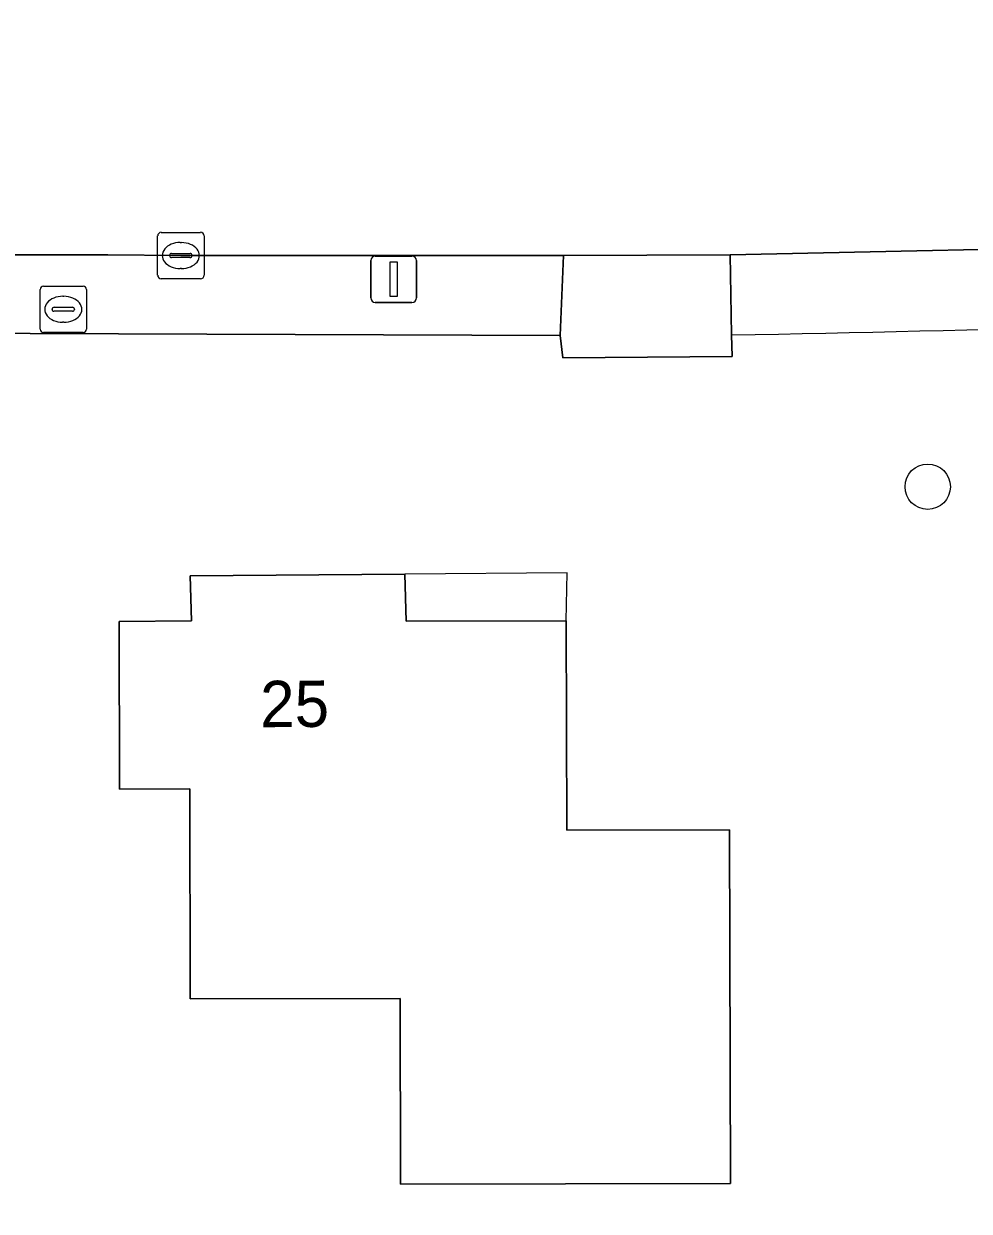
# Model space of a CAD drawing. Extents: x 162661 to 163484, y 380247 to 381230.
# Drawn here: x 163108.1 to 163128.5, y 380811.86 to 380837.48 of the extents above; entities that cross this region are included whole.
import ezdxf

# ---------------------------------------------------------------- set-up
doc = ezdxf.new("R2010")
doc.units = 0
for name, color, linetype in [('IMGEO_Boom', 7, 'Continuous'), ('IMGEO_Brandkraan', 7, 'Continuous'), ('IMGEO_Erf', 7, 'Continuous'), ('IMGEO_Kolk', 7, 'Continuous'), ('IMGEO_Lichtmast', 7, 'Continuous'), ('IMGEO_Pand', 7, 'Continuous'), ('IMGEO_Pand_nummerreeks', 7, 'Continuous'), ('IMGEO_Pand_overbouw', 7, 'Continuous'), ('IMGEO_Parkeervlak_halfverhard', 7, 'Continuous'), ('IMGEO_Rijbaan_lokaal_gesloten', 7, 'Continuous'), ('IMGEO_Voetpad_open', 7, 'Continuous')]:
    doc.layers.add(name, color=color, linetype=linetype)

msp = doc.modelspace()

# ---------------------------------------------------------------- linework, layer by layer
at = {"layer": 'IMGEO_Boom'}
msp.add_circle((163127.605, 380827.492), 0.489, dxfattribs=at)
at = {"layer": 'IMGEO_Brandkraan'}
for p, q in [((163108.452, 380830.893), (163108.452, 380831.745)), ((163108.527, 380831.819), (163109.379, 380831.819)), ((163109.453, 380831.745), (163109.453, 380830.893)), ((163108.94, 380831.599), (163108.965, 380831.599)), ((163108.711, 380831.313), (163108.711, 380831.325)), ((163109.149, 380831.276), (163108.751, 380831.276)), ((163108.754, 380831.362), (163109.152, 380831.362)), ((163109.195, 380831.325), (163109.195, 380831.313)), ((163108.963, 380831.039), (163108.938, 380831.039)), ((163109.379, 380830.819), (163108.527, 380830.819))]:
    msp.add_line(p, q, dxfattribs=at)
for points in [[(163108.452, 380830.893), (163108.452, 380831.745)], [(163108.527, 380831.819), (163109.379, 380831.819)], [(163109.453, 380831.745), (163109.453, 380830.893)], [(163109.379, 380830.819), (163108.527, 380830.819)]]:
    msp.add_lwpolyline(points, dxfattribs=at)
for centre, radius, start, end in [((163108.529, 380831.743), 0.0765, 91.552, 178.448), ((163108.529, 380831.743), 0.0765, 91.552, 178.448), ((163109.377, 380831.743), 0.0765, 1.552, 88.448), ((163109.377, 380831.743), 0.0765, 1.552, 88.448), ((163108.751, 380831.322), 0.0403, 85.8775, 175.7526), ((163108.748, 380831.312), 0.0366, 178.938, 274.7102), ((163109.152, 380831.319), 0.043, 264.8664, 352.4533), ((163109.156, 380831.324), 0.0386, 1.7309, 96.639), ((163108.529, 380830.895), 0.0765, 181.552, 268.448), ((163108.529, 380830.895), 0.0765, 181.552, 268.448), ((163109.377, 380830.895), 0.0765, 271.552, 358.448), ((163109.377, 380830.895), 0.0765, 271.552, 358.448)]:
    msp.add_arc(centre, radius, start, end, dxfattribs=at)
for centre, major_axis, ratio, start_param, end_param in [((163108.939, 380831.319), (-0.387, 0.002), 0.722429, 4.712389, 7.853982), ((163108.964, 380831.319), (-0.39, 0.002), 0.717154, 1.570796, 4.712389)]:
    msp.add_ellipse(centre, major_axis=major_axis, ratio=ratio, start_param=start_param, end_param=end_param, dxfattribs=at)
at = {"layer": 'IMGEO_Erf'}
msp.add_lwpolyline([(163123.374, 380830.767), (163123.388, 380830.302), (163119.732, 380830.269), (163119.673, 380830.754), (163106.322, 380830.801), (163103.397, 380830.811), (163103.788, 380827.01), (163107.334, 380784.216), (163107.736, 380779.339), (163120.148, 380780.444), (163121.048, 380780.505), (163121.933, 380780.565), (163124.339, 380780.727), (163127.759, 380780.998), (163130.169, 380781.233)], dxfattribs=at)
msp.add_lwpolyline([(163116.322, 380825.602), (163116.351, 380824.591), (163119.805, 380824.601), (163119.815, 380820.082), (163123.331, 380820.09), (163123.347, 380812.458), (163116.227, 380812.444), (163116.22, 380816.452), (163111.691, 380816.442), (163111.682, 380820.972), (163110.166, 380820.969), (163110.159, 380824.585), (163111.722, 380824.595), (163111.693, 380825.571)], close=True, dxfattribs=at)
msp.add_arc((163115.256, 381322.737), 492.037, 270.9453, 272.83681, dxfattribs=at)
at = {"layer": 'IMGEO_Kolk'}
for p, q in [((163111.064, 380832.979), (163111.916, 380832.979)), ((163110.989, 380832.053), (163110.989, 380832.905)), ((163111.477, 380832.759), (163111.502, 380832.759)), ((163111.99, 380832.905), (163111.99, 380832.053)), ((163111.248, 380832.473), (163111.248, 380832.485)), ((163111.291, 380832.522), (163111.689, 380832.522)), ((163111.732, 380832.485), (163111.732, 380832.473)), ((163111.686, 380832.436), (163111.288, 380832.436)), ((163111.916, 380831.979), (163111.064, 380831.979)), ((163111.5, 380832.199), (163111.475, 380832.199))]:
    msp.add_line(p, q, dxfattribs=at)
for points in [[(163111.064, 380832.979), (163111.916, 380832.979)], [(163110.989, 380832.053), (163110.989, 380832.905)], [(163111.99, 380832.905), (163111.99, 380832.053)], [(163111.916, 380831.979), (163111.064, 380831.979)]]:
    msp.add_lwpolyline(points, dxfattribs=at)
for centre, radius, start, end in [((163111.066, 380832.903), 0.0765, 91.552, 178.448), ((163111.066, 380832.903), 0.0765, 91.552, 178.448), ((163111.914, 380832.903), 0.0765, 1.552, 88.448), ((163111.914, 380832.903), 0.0765, 1.552, 88.448), ((163111.288, 380832.482), 0.0403, 85.8775, 175.7526), ((163111.285, 380832.472), 0.0366, 178.938, 274.7102), ((163111.689, 380832.479), 0.043, 264.8664, 352.4533), ((163111.693, 380832.484), 0.0386, 1.7309, 96.639), ((163111.066, 380832.055), 0.0765, 181.552, 268.448), ((163111.066, 380832.055), 0.0765, 181.552, 268.448), ((163111.914, 380832.055), 0.0765, 271.552, 358.448), ((163111.914, 380832.055), 0.0765, 271.552, 358.448)]:
    msp.add_arc(centre, radius, start, end, dxfattribs=at)
for centre, major_axis, ratio, start_param, end_param in [((163111.476, 380832.479), (-0.387, 0.002), 0.722429, 4.712389, 7.853982), ((163111.501, 380832.479), (-0.39, 0.002), 0.717154, 1.570796, 4.712389)]:
    msp.add_ellipse(centre, major_axis=major_axis, ratio=ratio, start_param=start_param, end_param=end_param, dxfattribs=at)
at = {"layer": 'IMGEO_Lichtmast'}
for p, q in [((163115.686, 380832.468), (163116.476, 380832.468)), ((163116.476, 380832.468), (163115.686, 380832.468)), ((163115.586, 380831.568), (163115.586, 380832.368)), ((163115.586, 380832.368), (163115.586, 380831.568)), ((163116.576, 380832.368), (163116.576, 380831.568)), ((163116.576, 380831.568), (163116.576, 380832.368)), ((163116.476, 380831.468), (163115.686, 380831.468)), ((163115.686, 380831.468), (163116.476, 380831.468))]:
    msp.add_line(p, q, dxfattribs=at)
msp.add_lwpolyline([(163116.006, 380832.343), (163116.156, 380832.343), (163116.156, 380831.593), (163116.006, 380831.593), (163116.006, 380832.343)], dxfattribs=at)
for centre, start, end in [((163115.686, 380832.368), 90, 180), ((163115.686, 380832.368), 90, 180), ((163116.476, 380832.368), 0, 90), ((163116.476, 380832.368), 360, 90), ((163115.686, 380831.568), 180, 270), ((163115.686, 380831.568), 180, 270), ((163116.476, 380831.568), 270, 0), ((163116.476, 380831.568), 270, 0)]:
    msp.add_arc(centre, 0.1, start, end, dxfattribs=at)
at = {"layer": 'IMGEO_Pand'}
msp.add_lwpolyline([(163116.322, 380825.602), (163111.693, 380825.571), (163111.722, 380824.595), (163110.159, 380824.585), (163110.166, 380820.969), (163111.682, 380820.972), (163111.691, 380816.442), (163116.22, 380816.452), (163116.227, 380812.444), (163123.347, 380812.458), (163123.331, 380820.09), (163119.815, 380820.082), (163119.805, 380824.601), (163116.351, 380824.591)], close=True, dxfattribs=at)
at = {"layer": 'IMGEO_Pand_overbouw'}
msp.add_lwpolyline([(163116.322, 380825.602), (163116.351, 380824.591), (163119.805, 380824.601), (163119.828, 380825.631)], close=True, dxfattribs=at)
at = {"layer": 'IMGEO_Parkeervlak_halfverhard'}
msp.add_lwpolyline([(163139.513, 380833.027), (163132.746, 380832.696), (163123.341, 380832.497), (163123.374, 380830.767)], dxfattribs=at)
msp.add_lwpolyline([(163119.744, 380832.482), (163111.49, 380832.479), (163109.911, 380832.496), (163107.657, 380832.494), (163106.381, 380832.492), (163106.322, 380830.801), (163119.673, 380830.754)], close=True, dxfattribs=at)
msp.add_arc((163115.256, 381322.737), 492.037, 270.9453, 272.83681, dxfattribs=at)
at = {"layer": 'IMGEO_Rijbaan_lokaal_gesloten'}
msp.add_lwpolyline([(163123.218, 380838.062), (163120.377, 380838.056), (163116.803, 380838.048), (163111.215, 380838.035), (163107.751, 380838.082), (163107.746, 380837.789), (163107.662, 380832.793), (163107.657, 380832.494), (163109.911, 380832.496), (163111.49, 380832.479), (163119.744, 380832.482), (163123.341, 380832.497), (163132.746, 380832.696), (163139.513, 380833.027), (163140.718, 380833.079), (163144.869, 380833.344), (163153.175, 380833.877), (163156.557, 380834.074), (163157.591, 380834.155)], dxfattribs=at)
at = {"layer": 'IMGEO_Voetpad_open'}
msp.add_lwpolyline([(163123.341, 380832.497), (163119.744, 380832.482), (163119.673, 380830.754), (163119.732, 380830.269), (163123.388, 380830.302), (163123.374, 380830.767)], close=True, dxfattribs=at)

# ---------------------------------------------------------------- texts
at = {"layer": 'IMGEO_Pand_nummerreeks'}
msp.add_text('25', height=1, rotation=0.3899, dxfattribs=at).set_placement((163113.204, 380822.302))

doc.saveas('drawing.dxf')
